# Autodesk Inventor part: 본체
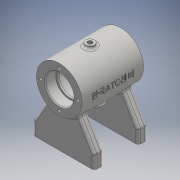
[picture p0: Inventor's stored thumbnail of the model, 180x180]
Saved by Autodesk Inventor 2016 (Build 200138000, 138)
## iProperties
Created: 2018-05
Part Number: 본체
Material: 일반
Document SubType Name: Modeling
Designer: USER
Density: 1 g/cm^3
Appearance: 기본값
Author: USER
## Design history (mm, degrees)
sketch "스케치1"
  geometry: C1 r 26 at (0, 0); 1 further point
  constraints: 1 centre point, 1 coincident
  dimensions: "d0" = 52 diameter of C1
extrude "돌출1" new body sketch "스케치1" stored distance "d1" = 70; taper "d2" = 0 deg
node "작업 평면1"
sketch "스케치2"
  geometry: L1 (0, 0)-(0, -65); L2 (0, -65)-(35, -65); L3 (35, -65)-(35, -50); L4 (35, -50)-(17.325, -19.386); L5 (0, -65)-(-35, -65); L6 (-35, -65)-(-35, -50); L7 (-35, -50)-(-17.325, -19.386); A1 r 26 centre (0, 0) between (-17.325, -19.386) and (17.325, -19.386)
  constraints: 14 end point, 3 symmetric about line, 2 point on circle, 2 vertical, 1 centre point, 1 coincident, 1 horizontal
  dimensions: "d4" = 65 distance of L1.start L1.end; "d5" = 35 distance of L1.end L2.end; "d6" = 15 distance of L2.end L3.end; "d7" = 30 deg angle of L3 L4; "d8" = 52 diameter of A1
extrude "돌출2" join sketch "스케치2" distance "d9" = 10; taper "d10" = 0 deg
sketch "스케치3"
  geometry: L1 (70, -10)-(0, -10) reference; 2 further points
  dimensions: "d11" = 20 horizontal distance of point (15, -5) point (35, 20); "d12" = 5 distance from line of L1 point (15, -5)
hole "구멍1" sketch "스케치3" at (15, -5) diameter "d13" = 4.134; stored, may be unused: countersink angle "d17" = 90 deg, drill point angle "d19" = 118 deg; dims "d14" = 8, "d15" = 4, "d16" = 2, "d18" = 10
sketch "스케치4"
  geometry: L1 (0, 0)-(46.636, 0); L2 (0, 0)-(-48.62, 0); L3 (35, -26)-(35, 26) reference; L4 (35, 16)-(23, 16); L5 (23, 16)-(23, 14); L6 (23, 14)-(21, 14); L7 (21, 14)-(21, 21); L8 (21, 21)-(-21, 21); L9 (-23, 16)-(-35, 16); L10 (-35, 26)-(-35, -26) reference; L11 (-35, 16)-(-35, 0); L12 (35, 16)-(35, 0); L13 (-35, 0)-(35, 0); L14 (-21, 21)-(-21, 14); L15 (-21, 14)-(-23, 14); L16 (-23, 14)-(-23, 16)
  constraints: 28 end point, 6 perpendicular, 4 horizontal, 2 midpoint, 2 point on line, 1 vertical
  dimensions: "d20" = 32 diameter of L4 L1; "d21" = 28 diameter of L6 L1; "d22" = 42 diameter of L8 L1; "d23" = 12 distance between parallel lines of L12 L5; "d25" = 28 diameter of L15 L2; "d26" = 32 diameter of L9 L2; "d27" = 12 distance between parallel lines of L11 L16; "d28" = 42 distance of L7.end L8.end; "d29" = 2 distance of L14.end L15.end
revolve "회전1" sketch "스케치4" stored, may be unused: angle "d30" = 90 deg
node "작업 평면4"
  node "작업 평면3"
sketch "스케치5"
  geometry: C1 r 5 at (0, 0); 1 further point
  constraints: 1 centre point, 1 coincident
  dimensions: "d32" = 10 diameter of C1
extrude "돌출3" join sketch "스케치5" stored distance "d33" = 10; taper "d34" = 0 deg
sketch "스케치6"
  geometry: 2 further points
  constraints: 1 coincident
hole "구멍2" sketch "스케치6" at (0, 0) diameter "d35" = 5.188; stored, may be unused: countersink angle "d39" = 90 deg, drill point angle "d41" = 118 deg; dims "d36" = 12, "d37" = 4, "d38" = 2, "d40" = 16
sketch "스케치7" dims "d42" = 42
  geometry: 3 further points
  constraints: 2 vertical alignment, 1 coincident, 2 other
hole "구멍3" sketch "스케치7" at (0, 21) diameter "d43" = 3.242; stored, may be unused: countersink angle "d47" = 90 deg, drill point angle "d49" = 118 deg; dims "d44" = 8, "d45" = 4, "d46" = 2, "d48" = 10
fillet "모깎기1" dims "d53" = 0.3
fillet "모깎기2" dims "d54" = 3
fillet "모깎기3" dims "d55" = 3
fillet "모깎기4" dims "d56" = 3
fillet "모깎기5" dims "d57" = 3
chamfer "모따기1" distance "d58" = 1; stored, may be unused: second distance "d59" = 2, angle "d60" = 45 deg
node "작업 평면5"
sketch "스케치9"
  geometry: L1 (0, 0)-(0, -40.059); L2 (0, 0)-(-9.919, -27.251)
  constraints: 4 end point, 1 vertical
  dimensions: "d63" = 29 distance of L1.start L2.end; "d64" = 20 deg angle of L1 L2
node "작업 평면6"
sketch "스케치10"
  geometry: C1 r 6 at (0, 0); 1 further point
  constraints: 1 centre point, 1 coincident
  dimensions: "d65" = 12 diameter of C1
extrude "돌출4" join sketch "스케치10" stored distance "d66" = 10; taper "d67" = 0 deg
sketch "스케치11"
  geometry: 2 further points
  constraints: 1 coincident
hole "구멍4" sketch "스케치11" at (0, 0) diameter "d68" = 5.188; stored, may be unused: countersink angle "d72" = 90 deg, drill point angle "d74" = 118 deg; dims "d69" = 12, "d70" = 4, "d71" = 2, "d73" = 16
fillet "모깎기6" dims "d75" = 2
node "작업 평면7"
sketch "스케치12"
  geometry: L1 (-35, 26)-(-35, -26) reference; 2 further points
  constraints: 1 other
  dimensions: "d77" = 35 distance from line of L1 point (0, 0); "d78" = 26 vertical distance of L1.start point (0, 0)
feature "엠보싱1" sketch "스케치12" dims "d79" = 0.5, "d80" = 0
node "솔리드1"
mirror "대칭1"
mirror "대칭2"
mirror "대칭3"
pattern_circular "원형 패턴1" dims angle "d51" = 360 deg
mirror "대칭4"
node "작업 평면2"
other parameters: "d31" = 3, "d61" = 20 deg, "d76" = 26
